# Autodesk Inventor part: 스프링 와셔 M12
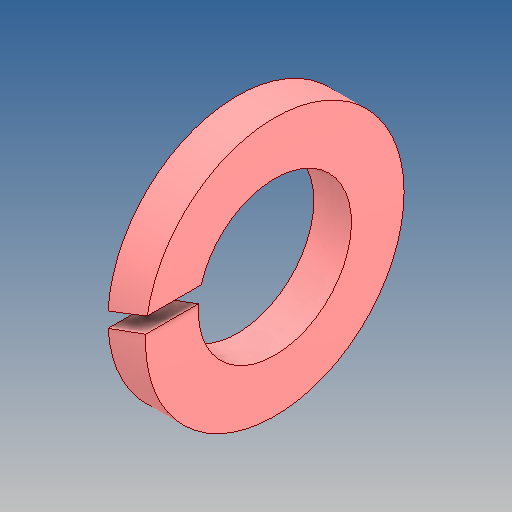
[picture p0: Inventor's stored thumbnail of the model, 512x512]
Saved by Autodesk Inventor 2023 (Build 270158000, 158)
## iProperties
Created: 2025-03
Part Number: 스프링 와셔 M12
Material: 강철, 연강
Description: 스프링 잠금 와셔
Document SubType Name: Modeling
Designer: Admin
Density: 7.85 g/cm^3
Appearance: 기본값
Author: jhkim
Sending System: Autodesk Inventor 2025
Preprocessor: ST-DEVELOPER v20
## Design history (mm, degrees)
node "스프링 와셔 M121"
node "솔리드1"
body "Solid1"
